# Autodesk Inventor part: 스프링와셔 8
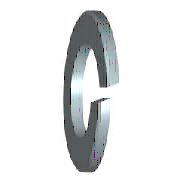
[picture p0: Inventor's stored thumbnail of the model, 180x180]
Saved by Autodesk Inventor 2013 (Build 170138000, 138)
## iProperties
IsCustomPart: 1
Created: 2012-02
Part Number: 스프링와셔 8
Material: 강철, 연강
Description: 스프링 잠금 와셔
Document SubType Name: Modeling
Standard: KS B 1324
Designer: mduedu
Standards Organization: KS
Language: ko-KR
Size Designation: 번호 3 - 8
Categories: <MemberInstance><Categories><Category DisplayName="조임쇠" InternalName="e4da775c-781d-43d5-af7c-5136215cf5a6" Mnemonic="FSTN"><Category DisplayName="와셔" InternalN
Density: 7.86 g/cm^3
Mass: 2.27751 g
Surface Area: 4.25113 cm^2
Volume: 0.289759 cm^3
Author: mduedu
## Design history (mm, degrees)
sketch "스케치1"
  geometry: C1 r 7.4 at (0, 0); C2 r 4.1 at (0, 0); 1 further point
  constraints: 2 centre point, 2 coincident
  dimensions: "d0" = 8.2 diameter of C2 (= SD1); "d1" = 14.8 diameter of C1 (= SD2)
extrude "본체" new body sketch "스케치1" distance "d2" = 2.5 (= SD); taper "d3" = 0 deg
sketch "스케치2"
  geometry: L1 (0, -4.1)-(0, 4.1) reference; L2 (2.5, 7.4)-(2.5, -7.4) reference; L3 (-1.2, 0)-(7.2, 0) reference; L4 (0, -0.5)-(2.5, 0.41); L5 (0, 0.5)-(2.5, 1.41)
  constraints: 4 end point, 4 point on line, 1 parallel
  dimensions: "d4" = 0.5 distance from line of L3 L4.start (= 0.2 x SD); "d5" = 0.5 distance from line of L3 L5.start (= 0.2 x SD); "d6" = 70 deg angle of L2 L4 (= FAWI)
extrude "절단부" cut sketch "스케치2" stored distance "d7" = 2.5 (= SD); taper "d8" = 0 deg
workaxis "Work Axis1"
workplane "Work Plane1"
body "Solid1"
other parameters: "SD1" = 8.2 [user parameter; used in 1 equation term], "SD2" = 14.8 [user parameter; used in 1 equation term], "SD" = 2.5 [user parameter; used in 4 equation terms], "FAWI" = 70 deg [user parameter; used in 1 equation term], "d9" = 0, "d10" = 0, "d11" = 0, "d12" = 0, "SDI" = 3.3 [user parameter], "NND" = 8 [user parameter]
